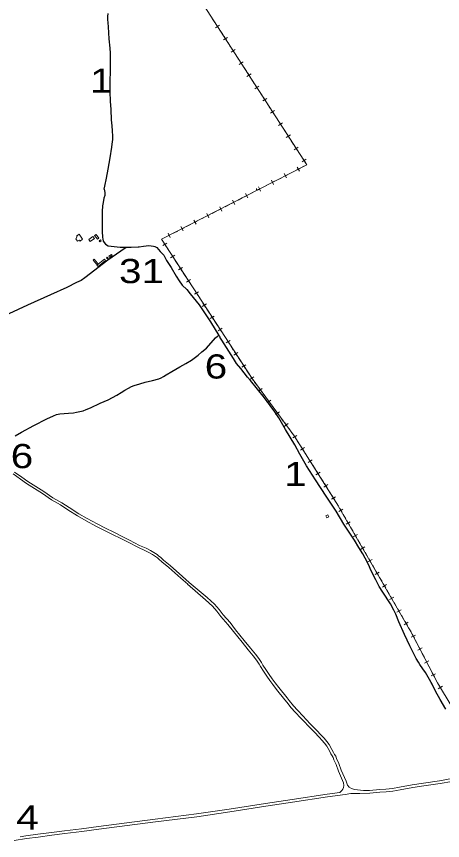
# Model space of a CAD drawing. Extents: x 476989 to 498418, y 4381813 to 4416555.
# Drawn here: x 486780 to 487660, y 4385096 to 4386800 of the extents above; entities that cross this region are included whole.
import ezdxf
from ezdxf.enums import TextEntityAlignment as Align

# ---------------------------------------------------------------- set-up
doc = ezdxf.new("R2010")
doc.units = 0
doc.header["$LTSCALE"] = 20
doc.linetypes.add('MEDIUM_DASHED', pattern=[4.5, 3, -1.5])
for name, color, linetype, lineweight in [('13', 7, 'Continuous', 13), ('34', 7, 'Continuous', 13), ('36', 7, 'Continuous', 13), ('38', 7, 'Continuous', 13), ('47', 7, 'Continuous', 13), ('48', 7, 'MEDIUM_DASHED', 13), ('54', 7, 'Continuous', 13), ('6', 7, 'Continuous', 25)]:
    doc.layers.add(name, color=color, linetype=linetype, lineweight=lineweight)

msp = doc.modelspace()

# ---------------------------------------------------------------- linework, layer by layer
at = {"layer": '34'}
for p, q in [((487184.9, 4386795.77), (487190.31, 4386787.37)), ((487199.93, 4386781.68), (487191.52, 4386776.26)), ((487193.02, 4386783.17), (487198.43, 4386774.77)), ((487201.14, 4386770.56), (487206.56, 4386762.16)), ((487216.17, 4386756.47), (487207.77, 4386751.05)), ((487209.26, 4386757.96), (487214.68, 4386749.56)), ((487217.39, 4386745.35), (487222.8, 4386736.95)), ((487232.42, 4386731.26), (487224.01, 4386725.84)), ((487225.51, 4386732.75), (487230.92, 4386724.35)), ((487233.63, 4386720.14), (487239.05, 4386711.74)), ((487248.66, 4386706.05), (487240.26, 4386700.63)), ((487241.75, 4386707.54), (487247.17, 4386699.14)), ((487249.88, 4386694.93), (487255.29, 4386686.53)), ((487264.91, 4386680.84), (487256.5, 4386675.42)), ((487257.99, 4386682.33), (487263.41, 4386673.93)), ((487266.12, 4386669.73), (487271.54, 4386661.32)), ((487281.15, 4386655.63), (487272.74, 4386650.21)), ((487274.24, 4386657.12), (487279.66, 4386648.72)), ((487282.36, 4386644.52), (487287.78, 4386636.11)), ((487297.4, 4386630.42), (487288.99, 4386625)), ((487290.48, 4386631.92), (487295.9, 4386623.51)), ((487298.61, 4386619.31), (487304.03, 4386610.9)), ((487313.64, 4386605.21), (487305.23, 4386599.79)), ((487306.73, 4386606.71), (487312.15, 4386598.3)), ((487314.85, 4386594.1), (487320.27, 4386585.69)), ((487329.88, 4386580), (487321.48, 4386574.59)), ((487322.97, 4386581.5), (487328.39, 4386573.09)), ((487331.1, 4386568.89), (487336.52, 4386560.48)), ((487346.13, 4386554.79), (487337.72, 4386549.38)), ((487339.22, 4386556.29), (487344.63, 4386547.88)), ((487347.34, 4386543.68), (487352.76, 4386535.27)), ((487362.37, 4386529.58), (487353.97, 4386524.17)), ((487355.46, 4386531.08), (487360.88, 4386522.67)), ((487363.59, 4386518.47), (487369, 4386510.06)), ((487378.62, 4386504.37), (487370.21, 4386498.96)), ((487371.71, 4386505.87), (487377.12, 4386497.46)), ((487366.94, 4386486.3), (487358.04, 4386481.73)), ((487364.77, 4386479.56), (487360.21, 4386488.46)), ((487326.91, 4386465.75), (487318.02, 4386461.18)), ((487340.26, 4386472.6), (487331.36, 4386468.03)), ((487338.09, 4386465.87), (487333.53, 4386474.76)), ((487353.6, 4386479.45), (487344.7, 4386474.88)), ((487300.23, 4386452.05), (487291.34, 4386447.49)), ((487313.58, 4386458.9), (487304.68, 4386454.34)), ((487311.41, 4386452.17), (487306.85, 4386461.07)), ((487260.22, 4386431.51), (487251.32, 4386426.95)), ((487258.05, 4386424.78), (487253.49, 4386433.68)), ((487273.55, 4386438.36), (487264.66, 4386433.79)), ((487280.6, 4386441.97), (487278, 4386440.64)), ((487282.94, 4386441.97), (487280.17, 4386447.37)), ((487286.9, 4386445.21), (487280.6, 4386441.97)), ((487284.73, 4386438.48), (487282.94, 4386441.97)), ((487233.54, 4386417.82), (487224.64, 4386413.25)), ((487231.37, 4386411.09), (487226.81, 4386419.98)), ((487246.87, 4386424.66), (487237.98, 4386420.1)), ((487193.51, 4386397.27), (487184.62, 4386392.7)), ((487206.86, 4386404.12), (487197.96, 4386399.55)), ((487204.69, 4386397.39), (487200.13, 4386406.29)), ((487220.19, 4386410.97), (487211.3, 4386406.4)), ((487166.83, 4386383.58), (487157.94, 4386379.01)), ((487180.18, 4386390.43), (487171.28, 4386385.86)), ((487178.01, 4386383.69), (487173.45, 4386392.59)), ((487126.82, 4386363.03), (487117.92, 4386358.47)), ((487124.65, 4386356.3), (487120.09, 4386365.2)), ((487140.15, 4386369.88), (487131.26, 4386365.31)), ((487153.5, 4386376.73), (487144.6, 4386372.16)), ((487151.33, 4386370), (487146.77, 4386378.89)), ((487100.14, 4386349.34), (487091.24, 4386344.77)), ((487097.97, 4386342.61), (487093.41, 4386351.5)), ((487113.47, 4386356.18), (487104.58, 4386351.62)), ((487090.92, 4386331.36), (487082.53, 4386325.92)), ((487084, 4386332.83), (487089.45, 4386324.45)), ((487092.17, 4386320.25), (487097.62, 4386311.87)), ((487107.25, 4386306.21), (487098.87, 4386300.76)), ((487100.34, 4386307.68), (487105.78, 4386299.29)), ((487108.5, 4386295.1), (487113.95, 4386286.71)), ((487123.58, 4386281.06), (487115.2, 4386275.61)), ((487116.67, 4386282.53), (487122.11, 4386274.14)), ((487124.84, 4386269.95), (487130.28, 4386261.56)), ((487139.92, 4386255.9), (487131.53, 4386250.46)), ((487133, 4386257.37), (487138.45, 4386248.99)), ((487141.17, 4386244.79), (487146.61, 4386236.41)), ((487156.25, 4386230.75), (487147.86, 4386225.31)), ((487149.33, 4386232.22), (487154.78, 4386223.83)), ((487157.5, 4386219.64), (487162.95, 4386211.25)), ((487172.58, 4386205.6), (487164.19, 4386200.15)), ((487165.66, 4386207.07), (487171.11, 4386198.68)), ((487173.83, 4386194.49), (487179.28, 4386186.1)), ((487188.91, 4386180.45), (487180.53, 4386175)), ((487182, 4386181.92), (487187.44, 4386173.53)), ((487190.16, 4386169.34), (487195.61, 4386160.95)), ((487205.24, 4386155.29), (487196.86, 4386149.85)), ((487198.33, 4386156.76), (487203.77, 4386148.38)), ((487206.5, 4386144.18), (487211.94, 4386135.8)), ((487221.58, 4386130.14), (487213.19, 4386124.69)), ((487214.66, 4386131.61), (487220.11, 4386123.22)), ((487222.83, 4386119.03), (487228.27, 4386110.64)), ((487237.91, 4386104.99), (487229.52, 4386099.54)), ((487230.99, 4386106.46), (487236.44, 4386098.07)), ((487239.16, 4386093.88), (487244.61, 4386085.49)), ((487254.24, 4386079.83), (487245.85, 4386074.39)), ((487247.32, 4386081.3), (487252.77, 4386072.92)), ((487255.49, 4386068.72), (487260.94, 4386060.34)), ((487270.57, 4386054.68), (487262.18, 4386049.23)), ((487272.26, 4386043.87), (487278.19, 4386035.82)), ((487288.14, 4386030.75), (487280.09, 4386024.81)), ((487281.15, 4386031.81), (487287.09, 4386023.76)), ((487290.05, 4386019.73), (487295.99, 4386011.68)), ((487305.94, 4386006.61), (487297.89, 4386000.67)), ((487298.95, 4386007.67), (487304.88, 4385999.62)), ((487307.85, 4385995.59), (487313.79, 4385987.54)), ((487323.74, 4385982.47), (487315.69, 4385976.54)), ((487316.75, 4385983.53), (487322.68, 4385975.48)), ((487325.65, 4385971.45), (487331.58, 4385963.41)), ((487341.53, 4385958.33), (487333.49, 4385952.4)), ((487334.54, 4385959.39), (487340.48, 4385951.34)), ((487343.44, 4385947.32), (487349.38, 4385939.27)), ((487359.4, 4385933.8), (487350.95, 4385928.47)), ((487360.51, 4385922.68), (487365.84, 4385914.22)), ((487375.4, 4385908.43), (487366.94, 4385903.1)), ((487368.5, 4385910), (487373.84, 4385901.54)), ((487376.5, 4385897.31), (487381.83, 4385888.85)), ((487391.39, 4385883.06), (487382.93, 4385877.73)), ((487384.5, 4385884.63), (487389.83, 4385876.17)), ((487392.5, 4385871.94), (487397.83, 4385863.48)), ((487407.39, 4385857.69), (487398.93, 4385852.36)), ((487400.49, 4385859.26), (487405.82, 4385850.8)), ((487408.49, 4385846.57), (487413.82, 4385838.11)), ((487423.38, 4385832.33), (487414.92, 4385826.99)), ((487416.48, 4385833.89), (487421.82, 4385825.43)), ((487424.48, 4385821.2), (487429.82, 4385812.74)), ((487439.37, 4385806.96), (487430.91, 4385801.62)), ((487432.48, 4385808.52), (487437.81, 4385800.06)), ((487454.83, 4385781.04), (487446.17, 4385776.04)), ((487448, 4385782.87), (487453, 4385774.21)), ((487455.5, 4385769.88), (487460.5, 4385761.22)), ((487469.82, 4385755.06), (487461.16, 4385750.06)), ((487463, 4385756.89), (487467.99, 4385748.23)), ((487470.49, 4385743.9), (487475.49, 4385735.24)), ((487484.82, 4385729.09), (487476.16, 4385724.09)), ((487477.99, 4385730.92), (487482.99, 4385722.26)), ((487485.49, 4385717.93), (487490.48, 4385709.27)), ((487499.81, 4385703.12), (487491.15, 4385698.12)), ((487492.98, 4385704.95), (487497.98, 4385696.29)), ((487500.48, 4385691.96), (487505.48, 4385683.29)), ((487514.8, 4385677.14), (487506.14, 4385672.14)), ((487507.97, 4385678.97), (487512.97, 4385670.31)), ((487515.47, 4385665.98), (487520.47, 4385657.32)), ((487529.79, 4385651.17), (487521.13, 4385646.17)), ((487522.96, 4385653), (487527.96, 4385644.34)), ((487530.46, 4385640.01), (487535.46, 4385631.35)), ((487544.79, 4385625.19), (487536.13, 4385620.2)), ((487537.96, 4385627.03), (487542.96, 4385618.36)), ((487545.45, 4385614.03), (487550.45, 4385605.37)), ((487559.78, 4385599.22), (487551.12, 4385594.22)), ((487552.95, 4385601.05), (487557.95, 4385592.39)), ((487560.45, 4385588.06), (487565.45, 4385579.4)), ((487574.77, 4385573.25), (487566.11, 4385568.25)), ((487567.94, 4385575.08), (487572.94, 4385566.42)), ((487575.44, 4385562.09), (487580.44, 4385553.43)), ((487589.76, 4385547.27), (487581.1, 4385542.27)), ((487582.93, 4385549.1), (487587.93, 4385540.44)), ((487590.43, 4385536.11), (487595.43, 4385527.45)), ((487604.67, 4385520.98), (487595.77, 4385516.4)), ((487604.8, 4385509.8), (487609.37, 4385500.91)), ((487618.39, 4385494.31), (487609.5, 4385489.74)), ((487611.66, 4385496.47), (487616.24, 4385487.58)), ((487618.53, 4385483.13), (487623.1, 4385474.24)), ((487632.12, 4385467.65), (487623.23, 4385463.07)), ((487625.39, 4385469.81), (487629.96, 4385460.92)), ((487632.25, 4385456.47), (487636.83, 4385447.58)), ((487639.11, 4385443.14), (487643.69, 4385434.25)), ((487645.85, 4385440.99), (487636.96, 4385436.41)), ((487660.04, 4385414.94), (487651.46, 4385409.81)), ((487653.19, 4385416.67), (487658.31, 4385408.09))]:
    msp.add_line(p, q, dxfattribs=at)
for points in [[(486520.9, 4388755.72), (486603, 4388633), (486612, 4388581), (486746, 4388393), (486776, 4388338), (486812, 4388290), (486879, 4388250), (487017, 4388189), (487152, 4388148), (487234, 4388140), (487360, 4387899), (487497, 4387717), (487531, 4387660), (487608, 4387440), (487634, 4387181), (487675, 4387065), (487547, 4387001), (487350, 4386921), (487175, 4386900), (487110, 4386912), (487380, 4386493), (487280.6, 4386441.97)], [(487379.83, 4386493.26), (487380, 4386493), (487371.38, 4386488.57)], [(487280.6, 4386441.97), (487080, 4386339), (487267, 4386051), (487354, 4385933), (487441, 4385795), (487598, 4385523), (487650, 4385422), (487680.1, 4385371.64)], [(487086.79, 4386342.49), (487080, 4386339), (487081.29, 4386337.02)], [(487263.66, 4386056.15), (487267, 4386051), (487269.29, 4386047.89)], [(487352.34, 4385935.25), (487354, 4385933), (487357.84, 4385926.91)], [(487440.48, 4385795.83), (487441, 4385795), (487445.51, 4385787.19)], [(487597.92, 4385523.13), (487598, 4385523), (487602.51, 4385514.24)], [(487645.98, 4385429.81), (487650, 4385422), (487650.63, 4385420.95)]]:
    msp.add_lwpolyline(points, dxfattribs=at)
at = {"layer": '36'}
for points in [[(486773.27, 4385853.94), (486788.78, 4385843.03), (486801.28, 4385834.3), (486817.65, 4385823.74), (486834.02, 4385813.25), (486852.64, 4385800.54), (486871.33, 4385789.79), (486886.69, 4385780.11), (486906.79, 4385767.31), (486924.22, 4385757.28), (486944.54, 4385746.26), (486962.36, 4385737.33), (486978.95, 4385729.07), (486996.26, 4385720.26), (487011.28, 4385712.94), (487032.42, 4385701.79), (487045.82, 4385695.72), (487055.01, 4385691.14), (487061.37, 4385687.37), (487067.84, 4385683.2), (487071.58, 4385680.27), (487074.28, 4385678), (487080.56, 4385672.07), (487094.87, 4385660.71), (487120.03, 4385638.46), (487134.03, 4385626.1)], [(486776.19, 4385857.99), (486791.65, 4385847.12), (486804.07, 4385838.45), (486820.36, 4385827.94), (486836.78, 4385817.42), (486855.3, 4385804.78), (486873.91, 4385794.07), (486889.37, 4385784.33), (486909.38, 4385771.58), (486926.66, 4385761.64), (486946.85, 4385750.69), (486964.59, 4385741.8), (486981.2, 4385733.53), (486998.49, 4385724.73), (487013.54, 4385717.39), (487034.62, 4385706.28), (487047.97, 4385700.24), (487057.41, 4385695.53), (487064, 4385691.62), (487070.75, 4385687.27), (487074.73, 4385684.15), (487077.6, 4385681.73), (487083.83, 4385675.85), (487098.08, 4385664.55), (487123.34, 4385642.2), (487137.34, 4385629.84)], [(487133.89, 4385626.23), (487170.51, 4385593.8), (487185.28, 4385580.75), (487194.21, 4385570.25), (487202.54, 4385559.33), (487217.08, 4385542.91), (487228.5, 4385527.97), (487246.35, 4385506.1), (487259.1, 4385490.16), (487269.28, 4385477.79), (487275.98, 4385469.12), (487281.5, 4385461), (487284.13, 4385455.86), (487290.6, 4385446.47), (487297.35, 4385435.87), (487304.04, 4385426.78), (487309.85, 4385418.74), (487317.59, 4385408.66), (487334.76, 4385387.33), (487339.11, 4385382.01), (487348.1, 4385370.63), (487356.37, 4385361.74), (487367.97, 4385348.97), (487374.33, 4385342.13), (487383.49, 4385332.54), (487395.25, 4385320.59), (487406.19, 4385309.18), (487411.15, 4385303.84), (487416.54, 4385297.24), (487421.12, 4385291.23), (487426.69, 4385281.31), (487429.91, 4385275.71), (487432.17, 4385271.1), (487434.44, 4385267.53), (487436.19, 4385263.29), (487440.62, 4385253.02), (487445.84, 4385239.74), (487455.81, 4385215.58)], [(487137.34, 4385629.84), (487174.37, 4385598.25), (487189.49, 4385584.88), (487198.79, 4385573.94), (487207.09, 4385563.07), (487221.62, 4385546.65), (487233.12, 4385531.62), (487250.93, 4385509.8), (487263.67, 4385493.87), (487273.88, 4385481.46), (487280.75, 4385472.58), (487286.58, 4385464.01), (487289.2, 4385458.89), (487295.51, 4385449.72), (487302.21, 4385439.2), (487308.8, 4385430.25), (487314.57, 4385422.26), (487322.22, 4385412.29), (487339.33, 4385391.04), (487343.7, 4385385.7), (487352.58, 4385374.47), (487360.7, 4385365.72), (487372.3, 4385352.95), (487378.61, 4385346.17), (487387.71, 4385336.64), (487399.47, 4385324.69), (487410.47, 4385313.22), (487415.59, 4385307.71), (487421.16, 4385300.88), (487426.05, 4385294.47), (487431.8, 4385284.22), (487435.11, 4385278.47), (487437.31, 4385273.99), (487439.69, 4385270.26), (487441.61, 4385265.57), (487446.06, 4385255.26), (487451.29, 4385241.96), (487461.05, 4385218.86)], [(487497.15, 4385199.42), (487509.69, 4385199.56), (487530.73, 4385201.64), (487543.2, 4385202.51), (487556.97, 4385203.85), (487571.79, 4385206.52), (487597.97, 4385211.35), (487621.23, 4385214.93), (487654.34, 4385219.7), (487679.81, 4385224.07)], [(486775.37, 4385096.2), (486800.8, 4385100.04), (486825.52, 4385103.44), (486853.12, 4385107.17), (486880.63, 4385110.38), (486915.74, 4385115.13), (486950.76, 4385119.43), (487008.87, 4385126.93), (487067.66, 4385134.49), (487152.91, 4385145.5), (487220.82, 4385155.63), (487295.65, 4385167.08), (487350.85, 4385175.59), (487422.95, 4385186.43), (487459.43, 4385191.37), (487470.68, 4385193.32), (487489.65, 4385193.71), (487510.01, 4385193.94), (487531.2, 4385196.06), (487543.67, 4385196.93), (487557.74, 4385198.3), (487572.8, 4385201.01), (487598.91, 4385205.81), (487622.06, 4385209.39), (487655.21, 4385214.16), (487679.8, 4385218.38)], [(487455.81, 4385215.58), (487456.62, 4385209.72), (487455.81, 4385205.68), (487454.49, 4385202.09), (487452.5, 4385199.34), (487448.32, 4385195.53)], [(487461.05, 4385218.86), (487463.98, 4385210.29), (487467.68, 4385206.41), (487472.37, 4385203.71), (487478.72, 4385201.9), (487497.15, 4385199.42)], [(486788.13, 4385103.8), (486799.99, 4385105.59), (486824.76, 4385108.99), (486852.42, 4385112.73), (486879.93, 4385115.94), (486915.02, 4385120.69), (486950.06, 4385124.99), (487008.15, 4385132.49), (487066.94, 4385140.05), (487152.14, 4385151.05), (487219.98, 4385161.17), (487294.79, 4385172.63), (487350, 4385181.14), (487422.16, 4385191.98), (487448.32, 4385195.53)]]:
    msp.add_lwpolyline(points, dxfattribs=at)
at = {"layer": '38', "linetype": 'MEDIUM_DASHED'}
for p, q in [((487276.18, 4386441.98), (487276.14, 4386444.17)), ((487276.19, 4386441.09), (487276.18, 4386441.98)), ((487277.97, 4386441.08), (487277.84, 4386441.33))]:
    msp.add_line(p, q, dxfattribs=at)
at = {"layer": '38'}
msp.add_line((487277.84, 4386441.08), (487277.84, 4386441.33), dxfattribs=at)
at = {"layer": '47'}
msp.add_lwpolyline([(486916.71, 4386339.17), (486909.73, 4386349.55), (486904.57, 4386345.72), (486905.46, 4386344.81), (486902.77, 4386340.27), (486906.37, 4386335.49), (486910.38, 4386337.38), (486911.85, 4386335.34)], close=True, dxfattribs=at)
at = {"layer": '48'}
msp.add_lwpolyline([(487419.36, 4385767.39), (487421.72, 4385763.16), (487425.79, 4385765.43), (487423.43, 4385769.66)], close=True, dxfattribs=at)
at = {"layer": '54'}
for points in [[(486944.91, 4386349.12), (486950.86, 4386341.52), (486947.77, 4386339.1), (486941.82, 4386346.7)], [(486938.33, 4386345.16), (486929.58, 4386338.88), (486932.77, 4386334.44), (486941.52, 4386340.72)], [(486955.08, 4386335.92), (486952.46, 4386334.01), (486951.03, 4386335.98), (486953.65, 4386337.89)], [(486938.52, 4386295.86), (486945.52, 4386287.62), (486947.81, 4386289.57), (486940.81, 4386297.81)], [(486964.25, 4386294.89), (486948.86, 4386282.59), (486946.63, 4386285.39), (486962.02, 4386297.69)], [(486968.03, 4386302.42), (486970.06, 4386299.97), (486968.12, 4386298.36), (486966.09, 4386300.81)], [(486978.35, 4386305.49), (486972.35, 4386301.67), (486970.9, 4386303.95), (486976.9, 4386307.77)]]:
    msp.add_lwpolyline(points, close=True, dxfattribs=at)
at = {"layer": '6'}
for points in [[(486969.07, 4386806.08), (486968.75, 4386799.56), (486968.75, 4386793.59), (486969.4, 4386786.44), (486969.8, 4386777.94), (486971.34, 4386753.69), (486973.54, 4386734.41), (486974.05, 4386723.9), (486973.93, 4386710.67), (486973.72, 4386700.87), (486973.6, 4386692.29), (486973.36, 4386660.37), (486973.36, 4386644.22), (486974.13, 4386624.85), (486975.53, 4386607.28), (486976.28, 4386585.73), (486977.3, 4386573.44), (486977.9, 4386563.02), (486978.72, 4386552.25), (486978.69, 4386545.45), (486977.95, 4386540.19), (486977.6, 4386535.73), (486976.62, 4386529.49), (486973.38, 4386507.65), (486969.33, 4386483.98), (486965.73, 4386465.44)], [(486965.73, 4386465.44), (486962.27, 4386449.05), (486960.98, 4386442.59)], [(486961.23, 4386442.68), (486962.96, 4386435.77), (486962.96, 4386429.29), (486961.03, 4386423.87), (486959.27, 4386415.13), (486958.3, 4386408.14), (486958.03, 4386404.51), (486957.73, 4386399.66), (486957.54, 4386385.95), (486957.43, 4386367.52), (486957.48, 4386355.76), (486957.48, 4386352.52), (486957.89, 4386346.03), (486958.44, 4386342.63), (486958.7, 4386339.75), (486959.71, 4386335.08), (486964.18, 4386329.2), (486969.87, 4386325.21)], [(487006.7, 4386322.35), (486996.11, 4386314.49), (486969.28, 4386295.81), (486921.9, 4386259.34), (486914.05, 4386253.61), (486904.73, 4386249.79), (486884.67, 4386239.67), (486850.72, 4386224), (486803, 4386202.78), (486764.38, 4386184.86), (486738.63, 4386173.19), (486716.6, 4386163.81), (486698.96, 4386159.51), (486686.97, 4386155.06), (486674.32, 4386151.21), (486667.46, 4386148.9)], [(486969.87, 4386325.21), (486994.51, 4386322.75), (487017.32, 4386322.57), (487031.66, 4386323.49), (487033.84, 4386323.76)], [(487033.84, 4386323.76), (487042.5, 4386325.14), (487053.91, 4386325.94), (487058.85, 4386325.87), (487063.33, 4386324.69), (487066.47, 4386324.42), (487068.98, 4386323.12), (487070.31, 4386321.9), (487077.31, 4386314.01), (487084.56, 4386306.18), (487090.4, 4386295.22), (487099.73, 4386280.83), (487110.28, 4386263.12), (487116.59, 4386253.34), (487122.76, 4386244.17), (487131.94, 4386235.26), (487139.31, 4386226.08), (487158.04, 4386203.31), (487181.5, 4386168.37), (487198.43, 4386139.94)], [(486777.82, 4385933.01), (486790.63, 4385940.11), (486816.11, 4385954.4), (486842.97, 4385967.98), (486856.8, 4385973.84), (486863.2, 4385976.89), (486870.1, 4385978.29), (486887.62, 4385979.51), (486898.46, 4385980.58), (486904.53, 4385981.38), (486911.03, 4385982.92), (486917.86, 4385984.51), (486924.28, 4385987.17), (486933.54, 4385990.54), (486953.2, 4386000.02), (486969.46, 4386007.19), (486978.94, 4386012.25), (486987.97, 4386017.06), (486996.64, 4386022.22), (487004.16, 4386027.04), (487011.57, 4386031.23), (487017.83, 4386034.46), (487023.45, 4386036.93), (487034.88, 4386040.13), (487046.43, 4386043.6), (487061.36, 4386047.05), (487074.18, 4386050.65), (487079.1, 4386052.94), (487083.98, 4386055.69), (487089.78, 4386059), (487101.5, 4386065.89), (487117.69, 4386075.07), (487130.52, 4386082.16), (487142.14, 4386089.51), (487155.67, 4386099.18), (487163.6, 4386106.12), (487172.67, 4386113.9), (487191.42, 4386135.09), (487195.78, 4386138.66)], [(487195.78, 4386138.66), (487198.43, 4386139.98), (487199.62, 4386138.92), (487200.54, 4386137.06)], [(487666.97, 4385367.8), (487655.53, 4385387.66), (487646.04, 4385404.85), (487638.87, 4385419.17), (487637.07, 4385422.61), (487633.76, 4385428.95), (487624.95, 4385443.57), (487619.44, 4385451.28), (487613.84, 4385460.27), (487610.6, 4385465.19), (487606.19, 4385472.22), (487600.82, 4385482.25), (487593.07, 4385498.8), (487581.97, 4385522.18), (487570.38, 4385548.55), (487564.1, 4385563.94), (487559.97, 4385572.22), (487552.83, 4385585.27), (487536.84, 4385609.75), (487529.21, 4385621.16), (487522.63, 4385634.9), (487513.12, 4385653.9), (487507.22, 4385666.93), (487500.95, 4385680.07), (487496.09, 4385688.73), (487487.69, 4385701.85), (487478.39, 4385717.04), (487456.26, 4385750.25), (487440.58, 4385777.2), (487420.22, 4385808.25), (487398.32, 4385841.52), (487379.63, 4385870.99), (487365.57, 4385895.03), (487355.43, 4385914.12), (487335.81, 4385945.95), (487322.23, 4385970.08), (487314.11, 4385982.06), (487304.47, 4385995.75), (487292.37, 4386011.32), (487278.39, 4386029.12), (487263.61, 4386047.36), (487257.87, 4386054.11), (487243.52, 4386071.62), (487234.89, 4386082.44), (487228.78, 4386092.37), (487204.73, 4386130.27), (487200.54, 4386137.07)]]:
    msp.add_lwpolyline(points, dxfattribs=at)

# ---------------------------------------------------------------- texts
at = {"layer": '13', "width": 1.25}
for s, p in [('1', (486955.68, 4386642.08)), ('31', (487038.72, 4386248.42)), ('6', (487192.42, 4386051.19)), ('6', (486791.76, 4385865.93)), ('1', (487356.58, 4385828.88)), ('4', (486803.07, 4385118.78))]:
    msp.add_text(s, height=50, dxfattribs=at).set_placement(p, align=Align.CENTER)

doc.saveas('drawing.dxf')
